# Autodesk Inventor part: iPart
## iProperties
Created: 2002-11
Part Number: iPart
Material: Default
Document SubType Name: Modeling
Designer: ***
Author: ***
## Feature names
1. Derived Body1 [Tagging]
